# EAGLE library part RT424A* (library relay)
Power PCB Relay polarized bistable version SCHRACK 2 pole 8 A Source: http://www.schrack.com/.. 5843.pdf
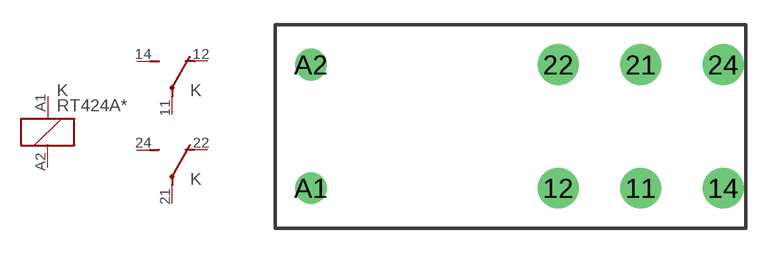
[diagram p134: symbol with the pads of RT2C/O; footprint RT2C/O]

Designator prefix K; gates 1=K 2=U 3=U

## RT424A05 (MPN: RT424A05; OC_FARNELL: unknown; OC_NEWARK: 48M7975), RT424A06 (MPN: RT424A06; OC_FARNELL: unknown; OC_NEWARK: 48M7976), RT424A12 (MPN: RT424A12; OC_FARNELL: unknown; OC_NEWARK: 48M7977), RT424A24 (MPN: RT424A24; OC_FARNELL: unknown; OC_NEWARK: 48M7978)  [RT2C/O]
11  2:P  pas
12  2:O  pas
14  2:S  pas
21  3:P  pas
22  3:O  pas
24  3:S  pas
A1  1:1  pas
A2  1:2  pas

## Footprint RT2C/O (pad centres in mm)
Power PCB Relay DC and AC-coil SCHRACK 2 pole 8 A Source: http://www.schrack.com/.. 5842.pdf
drill 1.3 pad 2.5 round: 11 7.56,-3.68; 12 2.52,-3.68; 14 12.6,-3.68; 21 7.56,3.88; 22 2.52,3.88; 24 12.6,3.88
drill 1.3 round: A1 -12.6,-3.68; A2 -12.6,3.88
